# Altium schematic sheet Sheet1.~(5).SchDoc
size A4
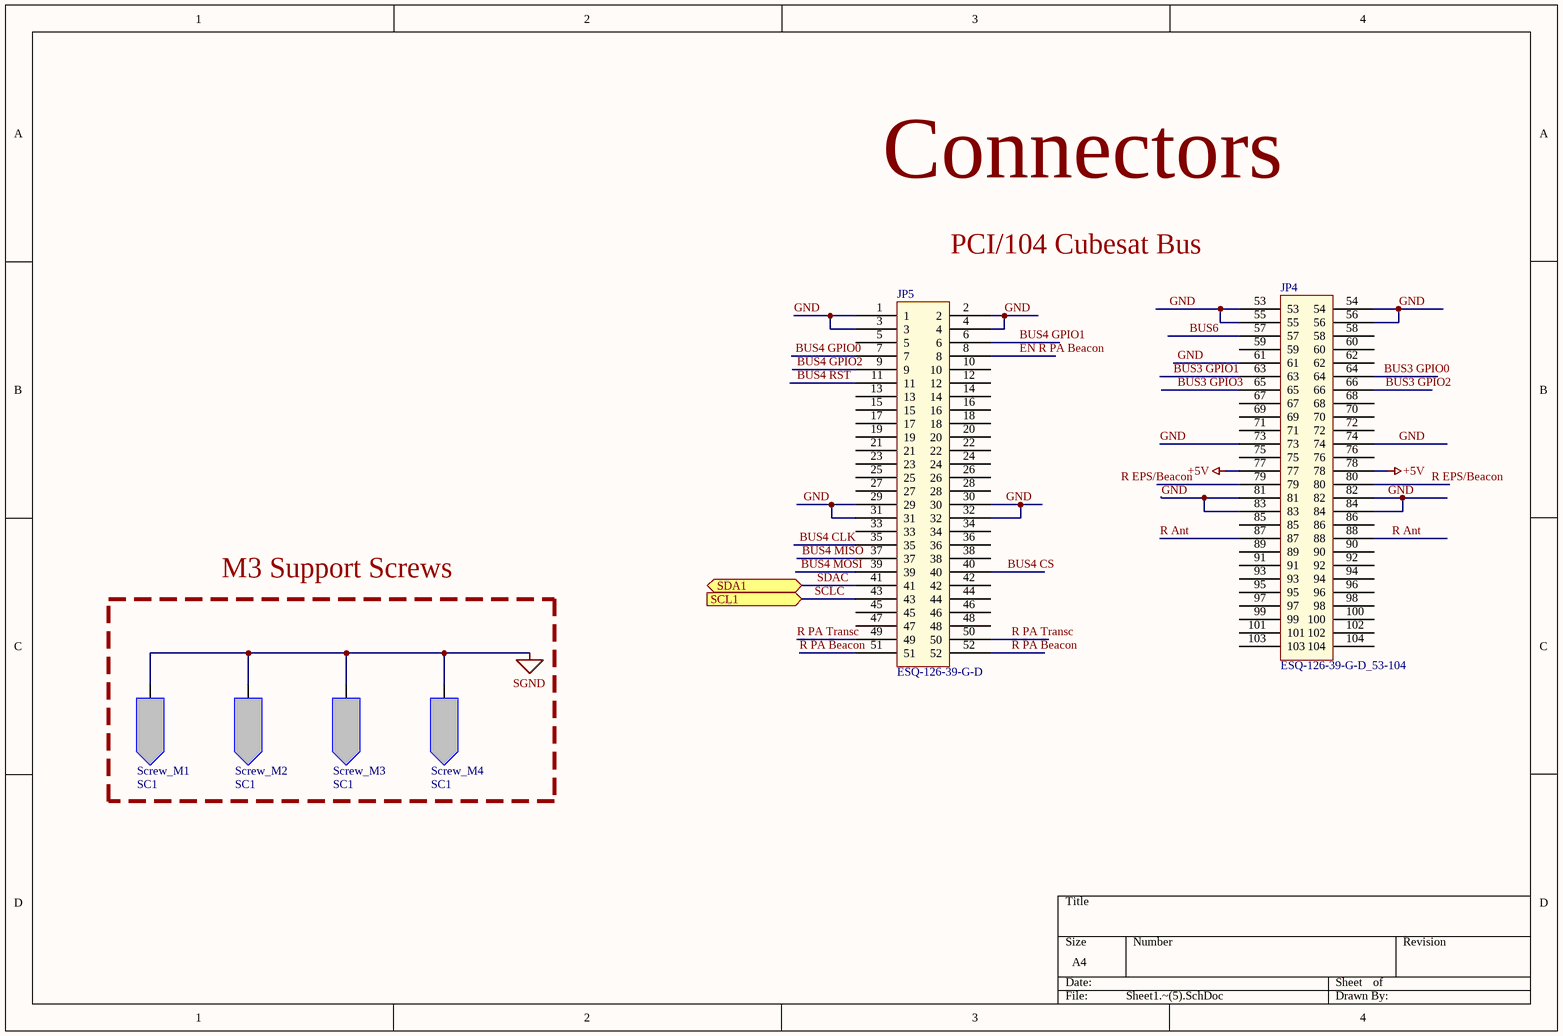
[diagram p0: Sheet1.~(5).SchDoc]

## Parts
JP4  ESQ-126-39-G-D_53-104  [ESQ-126-39-G-D_53_104]
JP5  ESQ-126-39-G-D  [ESQ-126-39-G-D]
Screw_M1  SC1  [Screw_M3]
Screw_M2  SC1  [Screw_M3]
Screw_M3  SC1  [Screw_M3]
Screw_M4  SC1  [Screw_M3]

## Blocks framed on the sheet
M3 Support Screws: Screw_M1-Screw_M4

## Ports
SCL1 (in), SDA1 (bidir)

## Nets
+5V: JP4.77 JP4.78
SGND: Screw_M1.1 Screw_M2.1 Screw_M3.1 Screw_M4.1
BUS3 GPIO0: JP4.64
BUS3 GPIO1: JP4.63
BUS3 GPIO2: JP4.66
BUS3 GPIO3: JP4.65
BUS4 CLK: JP5.35
BUS4 CS: JP5.40
BUS4 GPIO0: JP5.7
BUS4 GPIO1: JP5.6
BUS4 GPIO2: JP5.9
BUS4 MISO: JP5.37
BUS4 MOSI: JP5.39
BUS4 RST: JP5.11
BUS6: JP4.57
EN R PA Beacon: JP5.8
GND: JP4.53 JP4.54 JP4.55 JP4.56 JP4.61 JP4.73 JP4.74 JP4.81 JP4.82 JP4.83 JP4.84 JP5.1 JP5.2 JP5.3 JP5.4 JP5.29 JP5.30 JP5.31 JP5.32
R Ant: JP4.87 JP4.88
R EPS/Beacon: JP4.80
R PA Beacon: JP5.51 JP5.52
R PA Transc: JP5.49 JP5.50
SCLC: JP5.43 ; port SCL1
SDAC: JP5.41 ; port SDA1

Not connected (* = marked no-connect by the designer): JP4 58 59 60 62 67 68 69 70 71 72 75 76 79 85 86 89 90 91 92 93 94 95 96 97 98 99 100 101 102 103 104; JP5 5 10 12 13 14 15 16 17 18 19 20 21 22 23 24 25 26 27 28 33 34 36 38 42 44 45 46 47 48

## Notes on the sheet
- Connectors
- PCI/104 Cubesat Bus
- Labels drawn without touching a wire or pin: R EPS/Beacon

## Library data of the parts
JP4 = ESQ-126-39-G-D_53-104: Cubesat Header Connector; Shop: es.rs-online.com; Localización: Último cajón cajonera blanca entre Pablo y Luis; Reference: 254-6132
JP5 = ESQ-126-39-G-D: Cubesat Header Connector; Shop: es.rs-online.com; Localización: Último cajón cajonera blanca entre Pablo y Luis; Reference: 254-6132
Screw_M1-Screw_M4 = Screw_M3: Main CubeSAT bus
